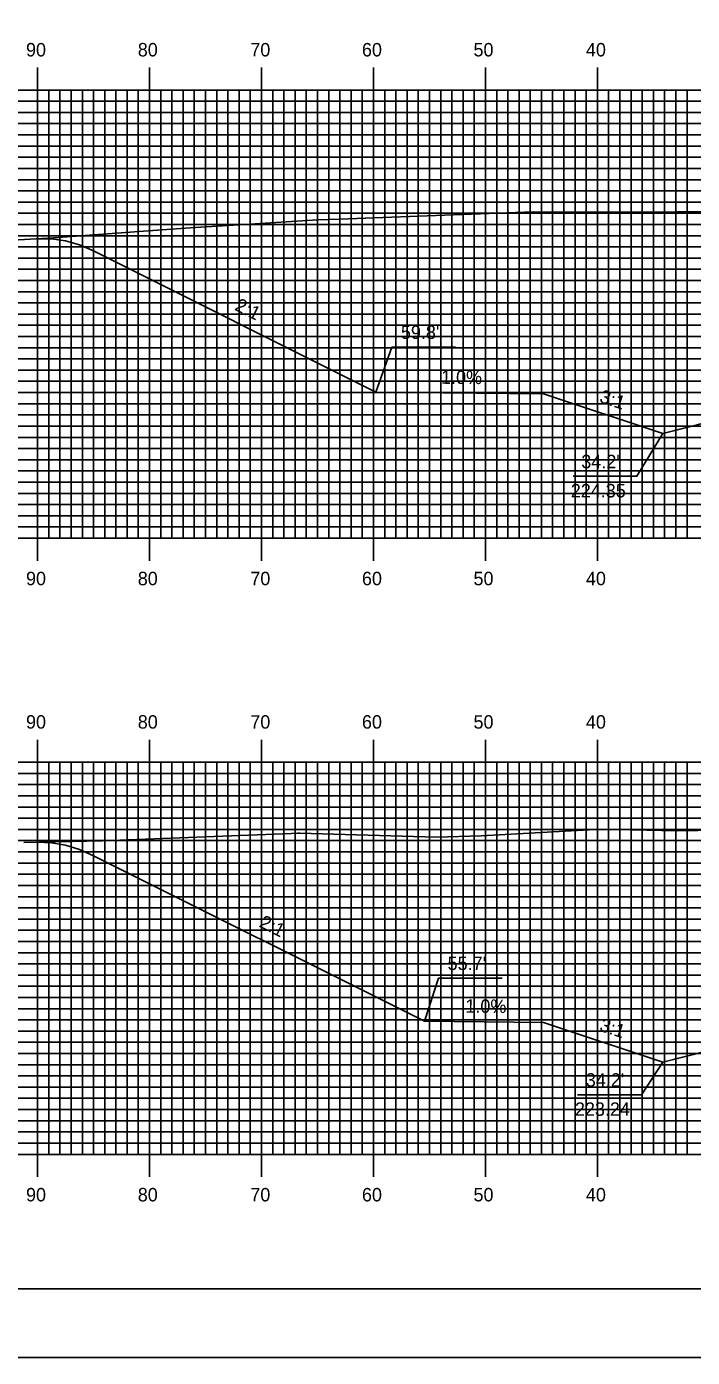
# Model space of a CAD drawing. Extents: x 1817276 to 1817620, y 442591 to 442811.
# Drawn here: x 1817351.1 to 1817410.6, y 442590.5 to 442709.3 of the extents above; entities that cross this region are included whole.
import ezdxf

# ---------------------------------------------------------------- set-up
doc = ezdxf.new("R2010")
doc.units = 0
for name, color, linetype in [('ANNOTATION', 7, 'Continuous'), ('BORDER', 7, 'Continuous'), ('D_Roadway_Centerline', 7, 'Continuous'), ('D_Roadway_SlopeLines', 7, 'Continuous'), ('H_V ANNOTATION', 7, 'Continuous'), ('MAJOR', 7, 'Continuous'), ('MINOR', 7, 'Continuous'), ('PLOT BOUNDARY', 7, 'Continuous'), ('S_Roadway_Centerline', 7, 'Continuous')]:
    doc.layers.add(name, color=color, linetype=linetype)

msp = doc.modelspace()

# ---------------------------------------------------------------- linework, layer by layer
at = {"layer": 'ANNOTATION'}
for points in [[(1817389.43, 442680.72), (1817383.74, 442680.72), (1817382.3, 442676.71)], [(1817399.92, 442669.19), (1817405.62, 442669.19), (1817407.93, 442673.01)], [(1817393.59, 442624.39), (1817387.9, 442624.39), (1817386.65, 442620.56)], [(1817400.32, 442613.99), (1817406.02, 442613.99), (1817407.93, 442616.91)]]:
    msp.add_lwpolyline(points, dxfattribs=at)
at = {"layer": 'BORDER'}
msp.add_lwpolyline([(1817292.5, 442596.67), (1817612.5, 442596.67), (1817612.5, 442806.67), (1817292.5, 442806.67)], close=True, dxfattribs=at)
at = {"layer": 'D_Roadway_Centerline'}
for points in [[(1817352.1, 442690.39), (1817353.35, 442690.39), (1817354.6, 442690.2), (1817355.85, 442689.84), (1817357.1, 442689.31), (1817382.3, 442676.71), (1817397.29, 442676.56), (1817407.93, 442673.01), (1817411.93, 442674.01), (1817422.1, 442676.56), (1817430.1, 442676.88), (1817442.1, 442677.12), (1817454.1, 442676.88), (1817462.1, 442676.56), (1817472.27, 442674.01), (1817476.27, 442673.01), (1817486.9, 442676.56), (1817496.05, 442676.65), (1817527.1, 442692.17), (1817528.35, 442692.72), (1817529.6, 442693.1), (1817530.85, 442693.31), (1817532.1, 442693.37)], [(1817352.1, 442636.54), (1817353.35, 442636.48), (1817354.6, 442636.26), (1817355.85, 442635.88), (1817357.1, 442635.33), (1817386.65, 442620.56), (1817397.29, 442620.45), (1817407.93, 442616.91), (1817411.93, 442617.91), (1817422.1, 442620.45), (1817430.1, 442620.77), (1817442.1, 442621.01), (1817454.1, 442620.77), (1817462.1, 442620.45), (1817472.27, 442617.91), (1817476.27, 442616.91), (1817486.9, 442620.45), (1817496.1, 442620.54), (1817527.1, 442636.04), (1817528.35, 442636.58), (1817529.6, 442636.96), (1817530.85, 442637.17), (1817532.1, 442637.21)]]:
    msp.add_lwpolyline(points, dxfattribs=at)
at = {"layer": 'D_Roadway_SlopeLines'}
for points in [[(1817397.29, 442676.56), (1817382.3, 442676.71), (1817357.1, 442689.31), (1817355.85, 442689.84), (1817354.6, 442690.2), (1817353.35, 442690.39), (1817352.1, 442690.39)], [(1817407.93, 442673.01), (1817397.29, 442676.56)], [(1817422.1, 442676.56), (1817407.93, 442673.01)], [(1817397.29, 442620.45), (1817386.65, 442620.56), (1817357.1, 442635.33), (1817355.85, 442635.88), (1817354.6, 442636.26), (1817353.35, 442636.48), (1817352.1, 442636.54)], [(1817407.93, 442616.91), (1817397.29, 442620.45)], [(1817422.1, 442620.45), (1817407.93, 442616.91)]]:
    msp.add_lwpolyline(points, dxfattribs=at)
at = {"layer": 'MAJOR'}
for p, q in [((1817352.1, 442705.67), (1817352.1, 442703.67)), ((1817362.1, 442705.67), (1817362.1, 442703.67)), ((1817372.1, 442705.67), (1817372.1, 442703.67)), ((1817382.1, 442705.67), (1817382.1, 442703.67)), ((1817392.1, 442705.67), (1817392.1, 442703.67)), ((1817402.1, 442705.67), (1817402.1, 442703.67)), ((1817302.1, 442703.67), (1817582.1, 442703.67)), ((1817302.1, 442703.67), (1817582.1, 442703.67)), ((1817352.1, 442663.67), (1817352.1, 442703.67)), ((1817362.1, 442663.67), (1817362.1, 442703.67)), ((1817372.1, 442663.67), (1817372.1, 442703.67)), ((1817382.1, 442663.67), (1817382.1, 442703.67)), ((1817392.1, 442663.67), (1817392.1, 442703.67)), ((1817402.1, 442663.67), (1817402.1, 442703.67)), ((1817302.1, 442698.67), (1817582.1, 442698.67)), ((1817302.1, 442693.67), (1817582.1, 442693.67)), ((1817302.1, 442688.67), (1817582.1, 442688.67)), ((1817302.1, 442683.67), (1817582.1, 442683.67)), ((1817302.1, 442678.67), (1817582.1, 442678.67)), ((1817302.1, 442673.67), (1817582.1, 442673.67)), ((1817302.1, 442668.67), (1817582.1, 442668.67)), ((1817302.1, 442663.67), (1817582.1, 442663.67)), ((1817302.1, 442663.67), (1817582.1, 442663.67)), ((1817352.1, 442661.66), (1817352.1, 442663.67)), ((1817362.1, 442661.66), (1817362.1, 442663.67)), ((1817372.1, 442661.66), (1817372.1, 442663.67)), ((1817382.1, 442661.66), (1817382.1, 442663.67)), ((1817392.1, 442661.66), (1817392.1, 442663.67)), ((1817402.1, 442661.66), (1817402.1, 442663.67)), ((1817352.1, 442645.67), (1817352.1, 442643.67)), ((1817362.1, 442645.67), (1817362.1, 442643.67)), ((1817372.1, 442645.67), (1817372.1, 442643.67)), ((1817382.1, 442645.67), (1817382.1, 442643.67)), ((1817392.1, 442645.67), (1817392.1, 442643.67)), ((1817402.1, 442645.67), (1817402.1, 442643.67)), ((1817302.1, 442643.67), (1817582.1, 442643.67)), ((1817302.1, 442643.67), (1817582.1, 442643.67)), ((1817352.1, 442608.67), (1817352.1, 442643.67)), ((1817362.1, 442608.67), (1817362.1, 442643.67)), ((1817372.1, 442608.67), (1817372.1, 442643.67)), ((1817382.1, 442608.67), (1817382.1, 442643.67)), ((1817392.1, 442608.67), (1817392.1, 442643.67)), ((1817402.1, 442608.67), (1817402.1, 442643.67)), ((1817302.1, 442638.67), (1817582.1, 442638.67)), ((1817302.1, 442633.67), (1817582.1, 442633.67)), ((1817302.1, 442628.67), (1817582.1, 442628.67)), ((1817302.1, 442623.67), (1817582.1, 442623.67)), ((1817302.1, 442618.67), (1817582.1, 442618.67)), ((1817302.1, 442613.67), (1817582.1, 442613.67)), ((1817302.1, 442608.67), (1817582.1, 442608.67)), ((1817302.1, 442608.67), (1817582.1, 442608.67)), ((1817352.1, 442606.66), (1817352.1, 442608.67)), ((1817362.1, 442606.66), (1817362.1, 442608.67)), ((1817372.1, 442606.66), (1817372.1, 442608.67)), ((1817382.1, 442606.66), (1817382.1, 442608.67)), ((1817392.1, 442606.66), (1817392.1, 442608.67)), ((1817402.1, 442606.66), (1817402.1, 442608.67))]:
    msp.add_line(p, q, dxfattribs=at)
at = {"layer": 'MINOR'}
for p, q in [((1817302.1, 442702.67), (1817582.1, 442702.67)), ((1817353.1, 442663.67), (1817353.1, 442703.67)), ((1817354.1, 442663.67), (1817354.1, 442703.67)), ((1817355.1, 442663.67), (1817355.1, 442703.67)), ((1817356.1, 442663.67), (1817356.1, 442703.67)), ((1817357.1, 442663.67), (1817357.1, 442703.67)), ((1817358.1, 442663.67), (1817358.1, 442703.67)), ((1817359.1, 442663.67), (1817359.1, 442703.67)), ((1817360.1, 442663.67), (1817360.1, 442703.67)), ((1817361.1, 442663.67), (1817361.1, 442703.67)), ((1817363.1, 442663.67), (1817363.1, 442703.67)), ((1817364.1, 442663.67), (1817364.1, 442703.67)), ((1817365.1, 442663.67), (1817365.1, 442703.67)), ((1817366.1, 442663.67), (1817366.1, 442703.67)), ((1817367.1, 442663.67), (1817367.1, 442703.67)), ((1817368.1, 442663.67), (1817368.1, 442703.67)), ((1817369.1, 442663.67), (1817369.1, 442703.67)), ((1817370.1, 442663.67), (1817370.1, 442703.67)), ((1817371.1, 442663.67), (1817371.1, 442703.67)), ((1817373.1, 442663.67), (1817373.1, 442703.67)), ((1817374.1, 442663.67), (1817374.1, 442703.67)), ((1817375.1, 442663.67), (1817375.1, 442703.67)), ((1817376.1, 442663.67), (1817376.1, 442703.67)), ((1817377.1, 442663.67), (1817377.1, 442703.67)), ((1817378.1, 442663.67), (1817378.1, 442703.67)), ((1817379.1, 442663.67), (1817379.1, 442703.67)), ((1817380.1, 442663.67), (1817380.1, 442703.67)), ((1817381.1, 442663.67), (1817381.1, 442703.67)), ((1817383.1, 442663.67), (1817383.1, 442703.67)), ((1817384.1, 442663.67), (1817384.1, 442703.67)), ((1817385.1, 442663.67), (1817385.1, 442703.67)), ((1817386.1, 442663.67), (1817386.1, 442703.67)), ((1817387.1, 442663.67), (1817387.1, 442703.67)), ((1817388.1, 442663.67), (1817388.1, 442703.67)), ((1817389.1, 442663.67), (1817389.1, 442703.67)), ((1817390.1, 442663.67), (1817390.1, 442703.67)), ((1817391.1, 442663.67), (1817391.1, 442703.67)), ((1817393.1, 442663.67), (1817393.1, 442703.67)), ((1817394.1, 442663.67), (1817394.1, 442703.67)), ((1817395.1, 442663.67), (1817395.1, 442703.67)), ((1817396.1, 442663.67), (1817396.1, 442703.67)), ((1817397.1, 442663.67), (1817397.1, 442703.67)), ((1817398.1, 442663.67), (1817398.1, 442703.67)), ((1817399.1, 442663.67), (1817399.1, 442703.67)), ((1817400.1, 442663.67), (1817400.1, 442703.67)), ((1817401.1, 442663.67), (1817401.1, 442703.67)), ((1817403.1, 442663.67), (1817403.1, 442703.67)), ((1817404.1, 442663.67), (1817404.1, 442703.67)), ((1817405.1, 442663.67), (1817405.1, 442703.67)), ((1817406.1, 442663.67), (1817406.1, 442703.67)), ((1817407.1, 442663.67), (1817407.1, 442703.67)), ((1817408.1, 442663.67), (1817408.1, 442703.67)), ((1817409.1, 442663.67), (1817409.1, 442703.67)), ((1817410.1, 442663.67), (1817410.1, 442703.67)), ((1817302.1, 442701.67), (1817582.1, 442701.67)), ((1817302.1, 442700.67), (1817582.1, 442700.67)), ((1817302.1, 442699.67), (1817582.1, 442699.67)), ((1817302.1, 442697.67), (1817582.1, 442697.67)), ((1817302.1, 442696.67), (1817582.1, 442696.67)), ((1817302.1, 442695.67), (1817582.1, 442695.67)), ((1817302.1, 442694.67), (1817582.1, 442694.67)), ((1817302.1, 442692.67), (1817582.1, 442692.67)), ((1817302.1, 442691.67), (1817582.1, 442691.67)), ((1817302.1, 442690.67), (1817582.1, 442690.67)), ((1817302.1, 442689.67), (1817582.1, 442689.67)), ((1817302.1, 442687.67), (1817582.1, 442687.67)), ((1817302.1, 442686.67), (1817582.1, 442686.67)), ((1817302.1, 442685.67), (1817582.1, 442685.67)), ((1817302.1, 442684.67), (1817582.1, 442684.67)), ((1817302.1, 442682.67), (1817582.1, 442682.67)), ((1817302.1, 442681.67), (1817582.1, 442681.67)), ((1817302.1, 442680.67), (1817582.1, 442680.67)), ((1817302.1, 442679.67), (1817582.1, 442679.67)), ((1817302.1, 442677.67), (1817582.1, 442677.67)), ((1817302.1, 442676.67), (1817582.1, 442676.67)), ((1817302.1, 442675.67), (1817582.1, 442675.67)), ((1817302.1, 442674.67), (1817582.1, 442674.67)), ((1817302.1, 442672.67), (1817582.1, 442672.67)), ((1817302.1, 442671.67), (1817582.1, 442671.67)), ((1817302.1, 442670.67), (1817582.1, 442670.67)), ((1817302.1, 442669.67), (1817582.1, 442669.67)), ((1817302.1, 442667.67), (1817582.1, 442667.67)), ((1817302.1, 442666.67), (1817582.1, 442666.67)), ((1817302.1, 442665.67), (1817582.1, 442665.67)), ((1817302.1, 442664.67), (1817582.1, 442664.67)), ((1817353.1, 442608.67), (1817353.1, 442643.67)), ((1817354.1, 442608.67), (1817354.1, 442643.67)), ((1817355.1, 442608.67), (1817355.1, 442643.67)), ((1817356.1, 442608.67), (1817356.1, 442643.67)), ((1817357.1, 442608.67), (1817357.1, 442643.67)), ((1817358.1, 442608.67), (1817358.1, 442643.67)), ((1817359.1, 442608.67), (1817359.1, 442643.67)), ((1817360.1, 442608.67), (1817360.1, 442643.67)), ((1817361.1, 442608.67), (1817361.1, 442643.67)), ((1817363.1, 442608.67), (1817363.1, 442643.67)), ((1817364.1, 442608.67), (1817364.1, 442643.67)), ((1817365.1, 442608.67), (1817365.1, 442643.67)), ((1817366.1, 442608.67), (1817366.1, 442643.67)), ((1817367.1, 442608.67), (1817367.1, 442643.67)), ((1817368.1, 442608.67), (1817368.1, 442643.67)), ((1817369.1, 442608.67), (1817369.1, 442643.67)), ((1817370.1, 442608.67), (1817370.1, 442643.67)), ((1817371.1, 442608.67), (1817371.1, 442643.67)), ((1817373.1, 442608.67), (1817373.1, 442643.67)), ((1817374.1, 442608.67), (1817374.1, 442643.67)), ((1817375.1, 442608.67), (1817375.1, 442643.67)), ((1817376.1, 442608.67), (1817376.1, 442643.67)), ((1817377.1, 442608.67), (1817377.1, 442643.67)), ((1817378.1, 442608.67), (1817378.1, 442643.67)), ((1817379.1, 442608.67), (1817379.1, 442643.67)), ((1817380.1, 442608.67), (1817380.1, 442643.67)), ((1817381.1, 442608.67), (1817381.1, 442643.67)), ((1817383.1, 442608.67), (1817383.1, 442643.67)), ((1817384.1, 442608.67), (1817384.1, 442643.67)), ((1817385.1, 442608.67), (1817385.1, 442643.67)), ((1817386.1, 442608.67), (1817386.1, 442643.67)), ((1817387.1, 442608.67), (1817387.1, 442643.67)), ((1817388.1, 442608.67), (1817388.1, 442643.67)), ((1817389.1, 442608.67), (1817389.1, 442643.67)), ((1817390.1, 442608.67), (1817390.1, 442643.67)), ((1817391.1, 442608.67), (1817391.1, 442643.67)), ((1817393.1, 442608.67), (1817393.1, 442643.67)), ((1817394.1, 442608.67), (1817394.1, 442643.67)), ((1817395.1, 442608.67), (1817395.1, 442643.67)), ((1817396.1, 442608.67), (1817396.1, 442643.67)), ((1817397.1, 442608.67), (1817397.1, 442643.67)), ((1817398.1, 442608.67), (1817398.1, 442643.67)), ((1817399.1, 442608.67), (1817399.1, 442643.67)), ((1817400.1, 442608.67), (1817400.1, 442643.67)), ((1817401.1, 442608.67), (1817401.1, 442643.67)), ((1817403.1, 442608.67), (1817403.1, 442643.67)), ((1817404.1, 442608.67), (1817404.1, 442643.67)), ((1817405.1, 442608.67), (1817405.1, 442643.67)), ((1817406.1, 442608.67), (1817406.1, 442643.67)), ((1817407.1, 442608.67), (1817407.1, 442643.67)), ((1817408.1, 442608.67), (1817408.1, 442643.67)), ((1817409.1, 442608.67), (1817409.1, 442643.67)), ((1817410.1, 442608.67), (1817410.1, 442643.67)), ((1817302.1, 442642.67), (1817582.1, 442642.67)), ((1817302.1, 442641.67), (1817582.1, 442641.67)), ((1817302.1, 442640.67), (1817582.1, 442640.67)), ((1817302.1, 442639.67), (1817582.1, 442639.67)), ((1817302.1, 442637.67), (1817582.1, 442637.67)), ((1817302.1, 442636.67), (1817582.1, 442636.67)), ((1817302.1, 442635.67), (1817582.1, 442635.67)), ((1817302.1, 442634.67), (1817582.1, 442634.67)), ((1817302.1, 442632.67), (1817582.1, 442632.67)), ((1817302.1, 442631.67), (1817582.1, 442631.67)), ((1817302.1, 442630.67), (1817582.1, 442630.67)), ((1817302.1, 442629.67), (1817582.1, 442629.67)), ((1817302.1, 442627.67), (1817582.1, 442627.67)), ((1817302.1, 442626.67), (1817582.1, 442626.67)), ((1817302.1, 442625.67), (1817582.1, 442625.67)), ((1817302.1, 442624.67), (1817582.1, 442624.67)), ((1817302.1, 442622.67), (1817582.1, 442622.67)), ((1817302.1, 442621.67), (1817582.1, 442621.67)), ((1817302.1, 442620.67), (1817582.1, 442620.67)), ((1817302.1, 442619.67), (1817582.1, 442619.67)), ((1817302.1, 442617.67), (1817582.1, 442617.67)), ((1817302.1, 442616.67), (1817582.1, 442616.67)), ((1817302.1, 442615.67), (1817582.1, 442615.67)), ((1817302.1, 442614.67), (1817582.1, 442614.67)), ((1817302.1, 442612.67), (1817582.1, 442612.67)), ((1817302.1, 442611.67), (1817582.1, 442611.67)), ((1817302.1, 442610.67), (1817582.1, 442610.67)), ((1817302.1, 442609.67), (1817582.1, 442609.67))]:
    msp.add_line(p, q, dxfattribs=at)
at = {"layer": 'PLOT BOUNDARY'}
msp.add_lwpolyline([(1817276.31, 442590.55), (1817616.31, 442590.55), (1817616.31, 442810.55), (1817276.31, 442810.55)], close=True, dxfattribs=at)
at = {"layer": 'S_Roadway_Centerline'}
for points in [[(1817344.15, 442689.94), (1817353.51, 442690.47), (1817361.97, 442691.11), (1817365.72, 442691.38), (1817370.54, 442691.68), (1817377.14, 442692.08), (1817379.05, 442692.13), (1817382.17, 442692.26), (1817396.37, 442692.79), (1817404.43, 442692.76), (1817414.08, 442692.84), (1817418.03, 442693.03), (1817430.26, 442693.46), (1817431.88, 442693.45), (1817437.57, 442693.65), (1817447.47, 442693.79), (1817458.17, 442693.51), (1817464.85, 442693.41), (1817472.07, 442693.71), (1817481.2, 442693.66)], [(1817350.88, 442636.52), (1817357.89, 442636.64), (1817374.78, 442637.31), (1817375.33, 442637.33), (1817375.51, 442637.33), (1817387.71, 442636.98), (1817391.72, 442637.1), (1817402.43, 442637.7), (1817409.21, 442637.56), (1817422.1, 442637.76), (1817426.54, 442637.69), (1817440.09, 442637.94), (1817443.47, 442637.98), (1817450.71, 442637.96), (1817454.26, 442637.9), (1817459.85, 442637.62), (1817467.72, 442637.74), (1817477.24, 442637.99)]]:
    msp.add_lwpolyline(points, dxfattribs=at)

# ---------------------------------------------------------------- texts
at = {"layer": 'ANNOTATION'}
for s, rotation, p in [('2:1', 333.4349, (1817369.63, 442684.08)), ('1.0%', 359.4271, (1817388.13, 442677.45)), ('3:1', 341.5651, (1817402.21, 442675.83)), ('2:1', 333.4349, (1817371.81, 442629.01)), ('1.0%', 359.4271, (1817390.3, 442621.32)), ('3:1', 341.5651, (1817402.21, 442619.72))]:
    msp.add_text(s, height=1.2, rotation=rotation, dxfattribs=at).set_placement(p)
for s, p in [("59.8'", (1817384.55, 442681.45)), ("34.2'", (1817400.66, 442669.91)), ('224.35', (1817399.72, 442667.31)), ("55.7'", (1817388.72, 442625.12)), ("34.2'", (1817401.06, 442614.71)), ('223.24', (1817400.09, 442612.11))]:
    msp.add_text(s, height=1.2, dxfattribs=at).set_placement(p)
at = {"layer": 'H_V ANNOTATION'}
for s, p in [('90', (1817351.07, 442706.67)), ('80', (1817361.05, 442706.67)), ('70', (1817371.1, 442706.67)), ('60', (1817381.07, 442706.67)), ('50', (1817391.03, 442706.67)), ('40', (1817401.07, 442706.67)), ('90', (1817351.07, 442659.47)), ('80', (1817361.05, 442659.47)), ('70', (1817371.1, 442659.47)), ('60', (1817381.07, 442659.47)), ('50', (1817391.03, 442659.47)), ('40', (1817401.07, 442659.47)), ('90', (1817351.07, 442646.67)), ('80', (1817361.05, 442646.67)), ('70', (1817371.1, 442646.67)), ('60', (1817381.07, 442646.67)), ('50', (1817391.03, 442646.67)), ('40', (1817401.07, 442646.67)), ('90', (1817351.07, 442604.47)), ('80', (1817361.05, 442604.47)), ('70', (1817371.1, 442604.47)), ('60', (1817381.07, 442604.47)), ('50', (1817391.03, 442604.47)), ('40', (1817401.07, 442604.47))]:
    msp.add_text(s, height=1.2, dxfattribs=at).set_placement(p)

doc.saveas('drawing.dxf')
